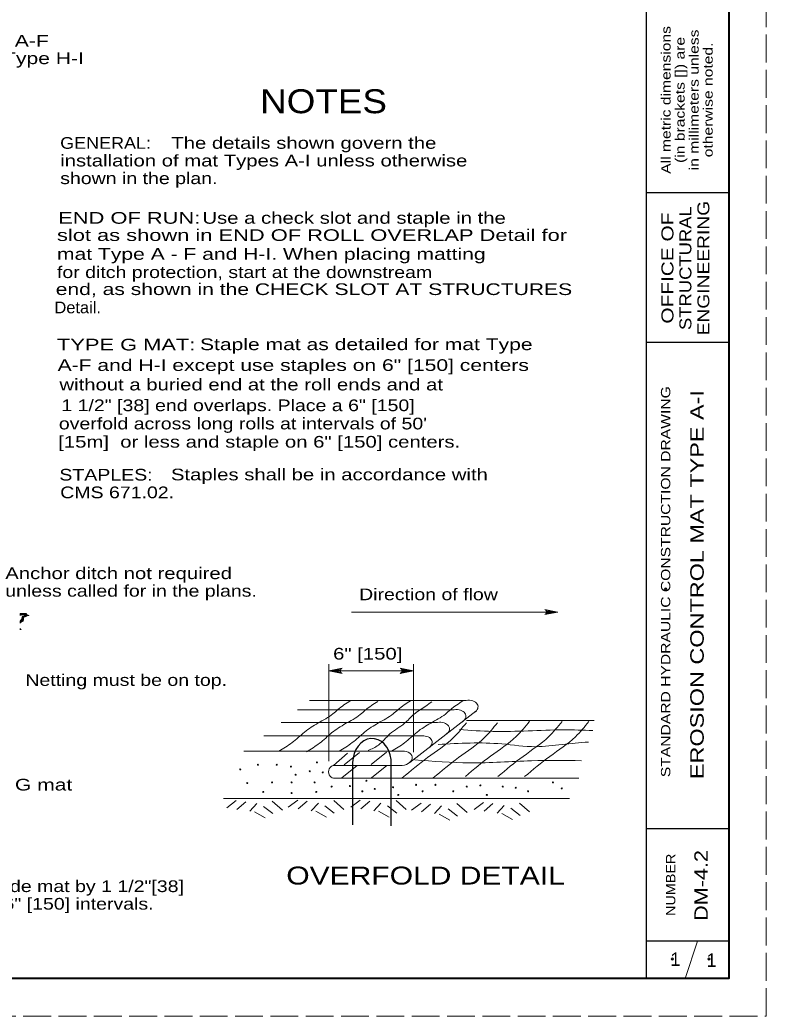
# Model space of a CAD drawing. Extents: x 1083.1 to 1117.1, y 719.4 to 741.4.
# Drawn here: x 1107.15 to 1117.13, y 719.35 to 732.67 of the extents above; entities that cross this region are included whole.
import ezdxf
from ezdxf.enums import TextEntityAlignment as Align

# ---------------------------------------------------------------- set-up
doc = ezdxf.new("R2010")
doc.units = 0
doc.header["$LTSCALE"] = 0.062
doc.header["$PDMODE"] = 32
doc.header["$PDSIZE"] = 0.031
doc.linetypes.add('LONG_DASHED', pattern=[7.5, 6, -1.5])
doc.layers.add('1', color=7, linetype='Continuous', lineweight=13)

msp = doc.modelspace()

# ---------------------------------------------------------------- linework, layer by layer
at = {"layer": '1', "lineweight": 25}
for p, q in [((1115.52642, 719.85408), (1115.52642, 740.85408)), ((1116.62642, 740.85408), (1116.62642, 719.85408)), ((1116.62642, 730.35408), (1115.52642, 730.35408)), ((1116.62642, 728.35408), (1115.52642, 728.35408)), ((1111.60092, 722.74192), (1111.60092, 721.90792)), ((1112.11558, 721.89525), (1112.11558, 722.78125)), ((1116.62642, 721.85408), (1115.52642, 721.85408)), ((1116.62642, 720.35408), (1115.52642, 720.35408))]:
    msp.add_line(p, q, dxfattribs=at)
at = {"layer": '1'}
for p, q in [((1107.15508, 724.70558), (1107.15508, 724.73292)), ((1107.15925, 724.7065), (1107.15925, 724.73475)), ((1107.16342, 724.70742), (1107.16342, 724.73642)), ((1107.16758, 724.70833), (1107.16758, 724.73667)), ((1107.17175, 724.70925), (1107.17175, 724.73675)), ((1107.17592, 724.71025), (1107.17592, 724.73683)), ((1107.17617, 724.61725), (1107.17617, 724.6585)), ((1107.18008, 724.71108), (1107.18008, 724.73692)), ((1107.18033, 724.62), (1107.18033, 724.67383)), ((1107.18425, 724.71208), (1107.18425, 724.737)), ((1107.1845, 724.62283), (1107.1845, 724.68917)), ((1107.18842, 724.71292), (1107.18842, 724.73708)), ((1107.18867, 724.62558), (1107.18867, 724.69592)), ((1107.19258, 724.71392), (1107.19258, 724.73717)), ((1107.19283, 724.62833), (1107.19283, 724.69842)), ((1107.19675, 724.71483), (1107.19675, 724.73725)), ((1107.197, 724.63183), (1107.197, 724.70092)), ((1107.20092, 724.71575), (1107.20092, 724.73733)), ((1107.20117, 724.6435), (1107.20117, 724.70342)), ((1107.20508, 724.71667), (1107.20508, 724.73742)), ((1107.20533, 724.681), (1107.20533, 724.70592)), ((1107.20533, 724.65508), (1107.20533, 724.65525)), ((1107.20925, 724.71775), (1107.20925, 724.7375)), ((1107.2095, 724.68292), (1107.2095, 724.70842)), ((1107.21342, 724.71992), (1107.21342, 724.73758)), ((1107.21367, 724.68483), (1107.21367, 724.71092)), ((1107.21758, 724.72208), (1107.21758, 724.73767)), ((1107.21783, 724.68667), (1107.21783, 724.71342)), ((1107.22175, 724.72425), (1107.22175, 724.73775)), ((1107.222, 724.68833), (1107.222, 724.71592)), ((1107.22592, 724.72642), (1107.22592, 724.73783)), ((1107.22617, 724.68942), (1107.22617, 724.71842)), ((1107.23008, 724.72858), (1107.23008, 724.73792)), ((1107.23033, 724.69058), (1107.23033, 724.72092)), ((1107.23425, 724.73075), (1107.23425, 724.738)), ((1107.2345, 724.69175), (1107.2345, 724.72342)), ((1107.23842, 724.73292), (1107.23842, 724.73808)), ((1107.23867, 724.69292), (1107.23867, 724.72525)), ((1107.24258, 724.73508), (1107.24258, 724.73817)), ((1107.24283, 724.69558), (1107.24283, 724.72292)), ((1107.24675, 724.73725), (1107.24675, 724.73825)), ((1107.247, 724.69892), (1107.247, 724.72067)), ((1107.25117, 724.70225), (1107.25117, 724.71842)), ((1107.25533, 724.70358), (1107.25533, 724.71608)), ((1107.25942, 724.70375), (1107.25942, 724.71383)), ((1107.26358, 724.704), (1107.26358, 724.71158)), ((1107.26775, 724.70425), (1107.26775, 724.70925)), ((1107.27192, 724.70442), (1107.27192, 724.707)), ((1107.27608, 724.70467), (1107.27608, 724.70475)), ((1111.58425, 724.75342), (1114.34433, 724.75342)), ((1114.18225, 724.72867), (1114.34433, 724.75342)), ((1114.18408, 724.77583), (1114.34433, 724.75342)), ((1114.18833, 724.73908), (1114.34433, 724.75342)), ((1114.18958, 724.76475), (1114.34433, 724.75342)), ((1114.19117, 724.75342), (1114.34433, 724.75342)), ((1107.15533, 724.60333), (1107.15533, 724.63583)), ((1107.15533, 724.51642), (1107.15533, 724.53508)), ((1107.1595, 724.60617), (1107.1595, 724.64)), ((1107.1595, 724.51717), (1107.1595, 724.532)), ((1107.16367, 724.60892), (1107.16367, 724.64417)), ((1107.16367, 724.51792), (1107.16367, 724.529)), ((1107.16783, 724.61167), (1107.16783, 724.64833)), ((1107.16783, 724.51867), (1107.16783, 724.526)), ((1107.172, 724.6145), (1107.172, 724.65242)), ((1107.172, 724.51942), (1107.172, 724.523)), ((1111.28425, 722.76108), (1111.28425, 724.05483)), ((1111.44633, 723.99283), (1111.28425, 723.96808)), ((1112.25167, 723.9905), (1112.41192, 723.96808)), ((1112.41192, 722.87942), (1112.41192, 724.05483)), ((1111.44025, 723.98242), (1111.28425, 723.96808)), ((1111.28425, 723.96808), (1112.41192, 723.96808)), ((1111.43742, 723.96808), (1111.28425, 723.96808)), ((1111.439, 723.95675), (1111.28425, 723.96808)), ((1111.4445, 723.94567), (1111.28425, 723.96808)), ((1112.24983, 723.94333), (1112.41192, 723.96808)), ((1112.25592, 723.95375), (1112.41192, 723.96808)), ((1112.25717, 723.97942), (1112.41192, 723.96808)), ((1112.25875, 723.96808), (1112.41192, 723.96808)), ((1111.02567, 723.57225), (1113.11783, 723.57225)), ((1110.86375, 723.44758), (1112.95592, 723.44758)), ((1113.24742, 723.42667), (1112.36492, 722.74367)), ((1110.64483, 723.2785), (1112.737, 723.2785)), ((1113.12208, 723.30583), (1114.8285, 723.30583)), ((1110.41258, 723.09825), (1112.50475, 723.09825)), ((1110.146, 722.89308), (1112.23817, 722.89308)), ((1111.34633, 722.70125), (1111.53225, 722.86808)), ((1111.48608, 722.71025), (1111.69117, 722.87483)), ((1111.8465, 722.71467), (1112.05158, 722.87925)), ((1111.34633, 722.70125), (1112.26317, 722.70125)), ((1111.45533, 722.53667), (1111.66042, 722.70125)), ((1111.85092, 722.53667), (1112.056, 722.70125)), ((1111.34633, 722.5345), (1114.62208, 722.5345)), ((1109.87267, 722.25933), (1114.49708, 722.25933)), ((1109.92, 722.13792), (1110.04617, 722.23258)), ((1110.05408, 722.11425), (1110.17233, 722.21675)), ((1110.22758, 722.09058), (1110.32217, 722.19308)), ((1110.40892, 722.15367), (1110.53508, 722.059)), ((1110.52717, 722.22467), (1110.66125, 722.10633)), ((1110.74008, 722.14583), (1110.86625, 722.2405)), ((1110.87417, 722.12217), (1110.99242, 722.22467)), ((1111.04767, 722.0985), (1111.14225, 722.201)), ((1111.229, 722.16158), (1111.35517, 722.06692)), ((1111.34725, 722.23258), (1111.48133, 722.11425)), ((1111.576, 722.14583), (1111.70217, 722.2405)), ((1111.71008, 722.12217), (1111.82833, 722.22467)), ((1111.88358, 722.0985), (1111.97817, 722.201)), ((1112.06492, 722.16158), (1112.19108, 722.06692)), ((1112.18317, 722.23258), (1112.31725, 722.11425)), ((1112.38825, 722.10642), (1112.51442, 722.20108)), ((1112.52233, 722.08275), (1112.64058, 722.18525)), ((1112.69583, 722.05908), (1112.79042, 722.16158)), ((1112.99542, 722.19317), (1113.1295, 722.07483)), ((1113.22408, 722.11433), (1113.35025, 722.209)), ((1113.35817, 722.09067), (1113.47642, 722.19317)), ((1113.53167, 722.067), (1113.62625, 722.1695)), ((1113.713, 722.13008), (1113.83917, 722.03542)), ((1113.83125, 722.20108), (1113.96533, 722.08275)), ((1110.29067, 722.08267), (1110.43258, 722.00375)), ((1111.11075, 722.09058), (1111.25267, 722.01167)), ((1111.94667, 722.09058), (1112.08858, 722.01167)), ((1112.75892, 722.05117), (1112.90083, 721.97225)), ((1112.87717, 722.12217), (1113.00333, 722.0275)), ((1113.59475, 722.05908), (1113.73667, 721.98017)), ((1116.04308, 719.85408), (1116.20975, 720.35408))]:
    msp.add_line(p, q, dxfattribs=at)
at = {"layer": '1', "linetype": 'LONG_DASHED'}
msp.add_lwpolyline([(1083.12642, 719.35408), (1117.12642, 719.35408), (1117.12642, 741.35408), (1083.12642, 741.35408)], close=True, dxfattribs=at)
at = {"layer": '1', "lineweight": 25}
msp.add_lwpolyline([(1116.62642, 719.85408), (1085.12642, 719.85408), (1085.12642, 740.85408)], dxfattribs=at)
at = {"layer": '1', "lineweight": 40}
msp.add_lwpolyline([(1085.12642, 740.85408), (1116.62642, 740.85408), (1116.62642, 719.85408), (1085.12642, 719.85408)], close=True, dxfattribs=at)
msp.add_lwpolyline([(1085.12642, 740.85408), (1116.62642, 740.85408), (1116.62642, 719.85408), (1085.12642, 719.85408)], close=True, dxfattribs=at)
at = {"layer": '1'}
for points in [[(1114.16733, 724.71808), (1114.34433, 724.75342), (1114.16733, 724.78883)], [(1111.46125, 724.00342), (1111.28425, 723.96808), (1111.46125, 723.93267)], [(1112.23492, 723.93275), (1112.41192, 723.96808), (1112.23492, 724.0035)]]:
    msp.add_lwpolyline(points, dxfattribs=at)
for centre, start, end in [((1114.1531, 724.75349), 292.08605, 67.91218), ((1111.47548, 723.96801), 112.08605, 247.91218), ((1112.22068, 723.96815), 292.08605, 67.91218)]:
    msp.add_arc(centre, 0.0382, start, end, dxfattribs=at)
for centre, major_axis, ratio, start_param, end_param in [((1112.96842, 723.35167), (-0.14568, -0.01899), 0.658393, 2.2307378, 4.71238898), ((1113.13033, 723.47633), (-0.14568, -0.01899), 0.658393, 2.18028872, 4.71238898), ((1112.7495, 723.18258), (-0.14568, -0.01899), 0.658393, 2.29706084, 4.71238898), ((1112.51725, 723.00233), (-0.14568, -0.01899), 0.658393, 2.21713058, 4.71238898), ((1112.25067, 722.79717), (-0.14568, -0.01899), 0.658393, 1.57079633, 4.71238898), ((1111.34633, 722.61788), (0, -0.08338), 0.81684, 3.14159265, 6.28318531)]:
    msp.add_ellipse(centre, major_axis=major_axis, ratio=ratio, start_param=start_param, end_param=end_param, dxfattribs=at)
at = {"layer": '1', "lineweight": 25}
msp.add_ellipse((1111.85925, 722.73567), major_axis=(0.00794, 0.32779), ratio=0.78812, start_param=4.87852867, end_param=7.8539922, dxfattribs=at)
at = {"layer": '1'}
for centre in [(1110.33453, 722.71228), (1110.58686, 722.71228), (1110.77611, 722.68862), (1111.12311, 722.74378), (1110.09795, 722.6492), (1110.8392, 722.5782), (1111.02845, 722.62553), (1111.20195, 722.6097), (1110.19261, 722.4677), (1110.52378, 722.47562), (1110.78403, 722.47562), (1111.09153, 722.47562), (1111.32028, 722.42037), (1111.5647, 722.42828), (1111.78553, 722.49928), (1111.89595, 722.38887), (1112.14036, 722.41253), (1112.44795, 722.44403), (1112.70811, 722.44403), (1113.12611, 722.42037), (1113.30745, 722.4362), (1113.60711, 722.42037), (1113.78061, 722.40462), (1114.27745, 722.47562), (1114.3957, 722.3967), (1110.40553, 722.34937), (1110.78403, 722.33362), (1111.1152, 722.34937), (1111.73028, 722.35728), (1112.21136, 722.30995), (1112.5347, 722.35728), (1112.9447, 722.35728), (1113.3942, 722.30995), (1113.9462, 722.35728)]:
    msp.add_ellipse(centre, major_axis=(0.00673, 0), ratio=0.999895, dxfattribs=at)
for points in [[(1110.61533, 722.89517), (1110.79042, 723.00775), (1110.95708, 723.1495), (1111.1405, 723.27042), (1111.33642, 723.39133), (1111.40308, 723.44967), (1111.56975, 723.56642)], [(1110.98208, 722.88683), (1111.15717, 722.99942), (1111.32383, 723.14117), (1111.50725, 723.26208), (1111.70317, 723.383), (1111.76983, 723.44133), (1111.9365, 723.55808)], [(1111.41967, 722.89517), (1111.59475, 723.00775), (1111.76142, 723.1495), (1111.94483, 723.27042), (1112.14075, 723.39133), (1112.20742, 723.44967), (1112.37408, 723.56642)], [(1111.80733, 722.9035), (1111.94483, 722.97442), (1112.099, 723.1245), (1112.29492, 723.26625), (1112.41575, 723.383), (1112.57833, 723.4955), (1112.6575, 723.55392)], [(1112.11983, 722.89383), (1112.29492, 723.00642), (1112.46158, 723.14817), (1112.645, 723.26908), (1112.84092, 723.39), (1112.90758, 723.44833), (1113.07425, 723.56508)], [(1112.264, 722.53667), (1112.60158, 722.80758), (1112.94333, 723.07025), (1113.1225, 723.27458)], [(1112.67842, 722.53667), (1113.016, 722.80758), (1113.35775, 723.07025), (1113.53692, 723.27458)], [(1113.10767, 722.5575), (1113.44525, 722.82842), (1113.787, 723.09108), (1113.96617, 723.29542)], [(1113.54117, 722.55333), (1113.87875, 722.82425), (1114.2205, 723.08692), (1114.39967, 723.29125)], [(1113.89958, 722.55333), (1114.23717, 722.82425), (1114.57892, 723.08692), (1114.75808, 723.29125)], [(1113.0285, 723.18283), (1113.47442, 723.15783), (1114.41633, 723.17867), (1114.81225, 723.17033)], [(1112.74508, 722.98275), (1113.59533, 722.99108), (1114.04542, 722.95358), (1114.39967, 722.98275), (1114.75392, 723.01608)], [(1112.4325, 722.77842), (1113.166, 722.73675), (1113.99125, 722.76592), (1114.65808, 722.76592)]]:
    msp.add_spline(points, degree=3, dxfattribs=at)
for p in [(1115.78383, 725.06008), (1116.21667, 725.06742), (1115.8745, 720.11783), (1116.36292, 720.11683)]:
    msp.add_point(p, dxfattribs=at)

# ---------------------------------------------------------------- texts
for s, height, width, p in [('All metric dimensions', 0.125, 1.25, (1115.85025, 731.59617)), ('in millimeters unless', 0.125, 1.25, (1116.22525, 731.59621)), ('(in brackets []) are', 0.125, 1.25, (1116.03775, 731.59617)), ('otherwise noted.', 0.125, 1.25, (1116.41275, 731.59617)), ('STRUCTURAL', 0.16, 1.15, (1116.12817, 729.34854)), ('ENGINEERING', 0.16, 1.2, (1116.36817, 729.34862)), ('OFFICE OF', 0.16, 1.3, (1115.88817, 729.34854)), ('STANDARD HYDRAULIC CONSTRUCTION DRAWING', 0.125, 1.25, (1115.84633, 725.15812)), ('EROSION CONTROL MAT TYPE A-I', 0.18, 1.3, (1116.29333, 725.11992)), ('NUMBER', 0.125, 1.15, (1115.91342, 721.10817)), ('DM-4.2', 0.18, 1.2, (1116.34775, 721.09892))]:
    msp.add_text(s, height=height, rotation=90, dxfattribs=dict(at, width=width)).set_placement(p, align=Align.CENTER)
for s, height, width, p in [('Type A-F', 0.156, 1.35, (1106.38083, 732.30858)), ('and Type H-I', 0.156, 1.35, (1106.38083, 732.07458)), ('NOTES', 0.32, 1.15, (1110.36408, 731.41842)), ('GENERAL:', 0.156, 1.15, (1107.69233, 730.94308)), ('The details shown govern the', 0.156, 1.3, (1109.17733, 730.94308)), ('installation of mat Types A-I unless otherwise', 0.156, 1.3, (1107.69233, 730.70708)), ('shown in the plan.', 0.156, 1.25, (1107.69233, 730.47108)), ('END OF RUN: ', 0.156, 1.4, (1107.66583, 729.94183)), ('Use a check slot and staple in the', 0.156, 1.3, (1109.59292, 729.9415)), ('slot as shown in END OF ROLL OVERLAP Detail for', 0.156, 1.4, (1107.64917, 729.71167)), ('mat Type A - F and H-I. When placing matting', 0.156, 1.35, (1107.64917, 729.45958)), ('for ditch protection, start at the downstream', 0.156, 1.25, (1107.64925, 729.21608)), ('end, as shown in the CHECK SLOT AT STRUCTURES', 0.156, 1.35, (1107.6325, 728.989)), ('Detail.', 0.156, 1.05, (1107.61583, 728.74533)), ('TYPE G MAT: ', 0.156, 1.4, (1107.64925, 728.2485)), ('Staple mat as detailed for mat Type ', 0.156, 1.35, (1109.56025, 728.25267)), ('A-F and H-I except use staples on 6" [150] centers', 0.156, 1.35, (1107.65742, 727.97467)), ('without a buried end at the roll ends and at', 0.156, 1.3, (1107.68242, 727.71433)), ('1 1/2" [38] end overlaps. Place a 6" [150]', 0.156, 1.25, (1107.70742, 727.43717)), ("overfold across long rolls at intervals of 50'", 0.156, 1.25, (1107.67417, 727.19358)), ('[15m]  or less and staple on 6" [150] centers.', 0.156, 1.3, (1107.66592, 726.94992)), ('STAPLES:', 0.156, 1.25, (1107.68092, 726.50992)), (' Staples shall be in accordance with', 0.156, 1.3, (1109.09683, 726.51267)), ('CMS 671.02.', 0.156, 1.25, (1107.69233, 726.27392)), ('Anchor ditch not required ', 0.156, 1.3, (1106.958, 725.19292)), ('unless called for in the plans.', 0.156, 1.25, (1106.958, 724.95825)), ('Direction of flow', 0.156, 1.25, (1111.68683, 724.91117)), ('6" [150]', 0.156, 1.3, (1111.33942, 724.11792)), ('Netting must be on top.', 0.156, 1.25, (1107.22633, 723.76625)), ('Type G mat', 0.156, 1.35, (1106.38308, 722.36833)), ('OVERFOLD DETAIL', 0.24, 1.25, (1110.714, 721.11175)), ('Overlap upgrade mat by 1 1/2"[38]', 0.156, 1.25, (1105.36892, 721.01125)), ('and staple at 6" [150] intervals.', 0.156, 1.25, (1105.36892, 720.77658))]:
    msp.add_text(s, height=height, dxfattribs=dict(at, width=width)).set_placement(p)
for p in [(1115.91427, 720.02417), (1116.3971, 720.01158)]:
    msp.add_text('1', height=0.18, dxfattribs=at).set_placement(p, align=Align.CENTER)

doc.saveas('drawing.dxf')
